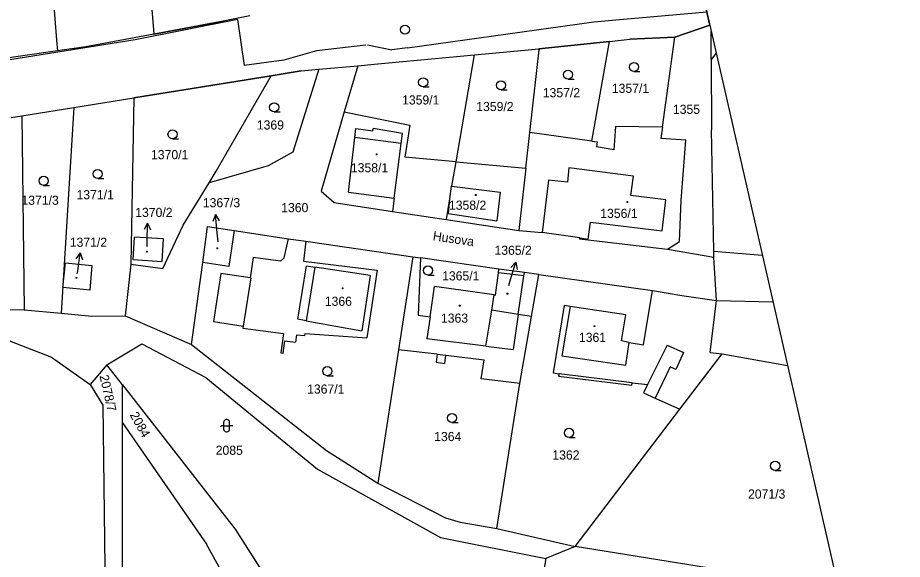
# Model space of a CAD drawing. Extents: x -805730 to -804640, y -1150889 to -1150366.
# Drawn here: x -804785.9 to -804640.4, y -1150604.7 to -1150515.7 of the extents above; entities that cross this region are included whole.
import ezdxf

# ---------------------------------------------------------------- set-up
doc = ezdxf.new("R2010")
doc.units = 0
for name, color, linetype in [('Default', 7, 'Continuous'), ('formát', 7, 'Continuous'), ('kilometráž - vrstava 7', 7, 'Continuous'), ('kn_celek - Cisla parcel pomocna', 7, 'Continuous'), ('kn_celek - Cisla pozemkovych parcel', 7, 'Continuous'), ('kn_celek - Cisla stavebnich parcel', 7, 'Continuous'), ('kn_celek - Dalsi prvky mapy popis', 7, 'Continuous'), ('kn_celek - Hranice parcel', 7, 'Continuous'), ('kn_celek - Vnitrni kresby', 7, 'Continuous'), ('kn_celek - Znacky budov', 7, 'Continuous'), ('kn_celek - Znacky kultur', 7, 'Continuous'), ('plochy - SZDC', 7, 'Continuous'), ('PSR_C2_2_trasa_Vimperk - Kabelová trasa', 7, 'Continuous')]:
    doc.layers.add(name, color=color, linetype=linetype)

# ---------------------------------------------------------------- blocks, each defined once
blk = doc.blocks.new('304')
at = {"layer": 'Default'}
blk.add_line((-0.1, 0), (9.9, 0), dxfattribs=at)
blk.add_circle((-0.1, 7.5), 7.5, dxfattribs=at)
blk = doc.blocks.new('316')
at = {"layer": 'Default'}
for p, q in [((-5, 15.5), (-5, 4.5)), ((0.5, 20), (-0.5, 20)), ((5, 4.5), (5, 15.5)), ((-8.3, 10), (-10, 8.1)), ((-5, 10), (-8.3, 10)), ((-5, 10), (5, 10)), ((-0.5, 0), (0.5, 0)), ((10, 10), (5, 10))]:
    blk.add_line(p, q, dxfattribs=at)
for centre, start, end in [((-0.5, 15.5), 90, 180), ((0.5, 15.5), 0, 90), ((-0.5, 4.5), 180, 270), ((0.5, 4.5), 270, 0)]:
    blk.add_arc(centre, 4.5, start, end, dxfattribs=at)
blk = doc.blocks.new('402')
at = {"layer": 'Default'}
for p, q in [((-0.8, 0.8), (0.7, 0.8)), ((-0.8, 0.8), (-0.8, -0.7)), ((0.7, 0.8), (0.7, -0.7)), ((0.7, -0.7), (-0.8, -0.7))]:
    blk.add_line(p, q, dxfattribs=at)
blk = doc.blocks.new('Z61')
at = {"layer": 'Default'}
for p, q in [((0, 0), (30, 0)), ((30, 0), (19.2, 5.3)), ((30, 0), (19.2, -5.3))]:
    blk.add_line(p, q, dxfattribs=at)

msp = doc.modelspace()

# ---------------------------------------------------------------- linework, layer by layer
at = {"layer": 'formát'}
msp.add_line((-804706.6, -1150365.97), (-804640.43, -1150655.5), dxfattribs=at)
at = {"layer": 'kilometráž - vrstava 7'}
msp.add_circle((-804722.2, -1150517.67), 0.75, dxfattribs=at)
at = {"layer": 'kn_celek - Cisla parcel pomocna'}
for p, q in [((-804752.95, -1150552.55), (-804753.1, -1150551.06)), ((-804764.64, -1150553.33), (-804764.63, -1150552.48)), ((-804776.1, -1150557.81), (-804776.04, -1150557.34)), ((-804705.14, -1150559.73), (-804704.85, -1150558.77))]:
    msp.add_line(p, q, dxfattribs=at)
at = {"layer": 'kn_celek - Hranice parcel'}
for p, q in [((-804765.53, -1150494.1), (-804763.55, -1150517.73)), ((-804781.47, -1150495.86), (-804779.51, -1150519.42)), ((-804747.72, -1150515.43), (-804751.83, -1150516.2)), ((-804763.49, -1150518.4), (-804751.83, -1150516.2)), ((-804763.55, -1150517.73), (-804763.49, -1150518.4)), ((-804672.1, -1150516.95), (-804677.85, -1150518.93)), ((-804671.87, -1150522.56), (-804671.85, -1150518.01)), ((-804779.51, -1150519.42), (-804779.36, -1150521.18)), ((-804763.49, -1150518.4), (-804774.72, -1150520.52)), ((-804688.56, -1150519.6), (-804700.23, -1150520.83)), ((-804691.48, -1150536.01), (-804688.56, -1150519.6)), ((-804688.56, -1150519.6), (-804685.22, -1150519.25)), ((-804677.85, -1150518.93), (-804685.22, -1150519.25)), ((-804679.88, -1150533.68), (-804677.85, -1150518.93)), ((-804779.36, -1150521.18), (-804795.05, -1150523.42)), ((-804774.72, -1150520.52), (-804779.36, -1150521.18)), ((-804710.79, -1150521.81), (-804700.23, -1150520.83)), ((-804701.68, -1150534.6), (-804700.17, -1150521.02)), ((-804700.23, -1150520.83), (-804700.17, -1150521.02)), ((-804727.28, -1150523.34), (-804710.79, -1150521.81)), ((-804713.82, -1150539.42), (-804710.79, -1150521.81)), ((-804671.04, -1150521.56), (-804671.87, -1150522.56)), ((-804671.87, -1150522.56), (-804671.82, -1150534.17)), ((-804736.36, -1150524.18), (-804740.64, -1150537.81)), ((-804739.31, -1150524.46), (-804736.36, -1150524.18)), ((-804736.36, -1150524.18), (-804729.97, -1150523.63)), ((-804729.97, -1150523.63), (-804732.19, -1150531.16)), ((-804729.97, -1150523.63), (-804727.28, -1150523.34)), ((-804744.2, -1150525.25), (-804766.8, -1150528.89)), ((-804753.24, -1150540.95), (-804744.2, -1150525.25)), ((-804739.31, -1150524.46), (-804744.2, -1150525.25)), ((-804776.65, -1150530.47), (-804766.8, -1150528.89)), ((-804766.8, -1150528.89), (-804767.28, -1150556.21)), ((-804785.22, -1150531.85), (-804776.65, -1150530.47)), ((-804776.65, -1150530.47), (-804778.78, -1150564.3)), ((-804732.19, -1150531.16), (-804735.99, -1150544.25)), ((-804732.19, -1150531.16), (-804721.42, -1150533.39)), ((-804786.96, -1150532.13), (-804785.22, -1150531.85)), ((-804785.22, -1150531.85), (-804784.86, -1150563.74)), ((-804721.42, -1150533.39), (-804722.26, -1150538.65)), ((-804687.61, -1150533.6), (-804687.89, -1150537.42)), ((-804679.88, -1150533.68), (-804687.61, -1150533.6)), ((-804679.88, -1150533.68), (-804680.14, -1150535.59)), ((-804671.45, -1150554.09), (-804671.82, -1150534.17)), ((-804702.34, -1150540.46), (-804701.68, -1150534.6)), ((-804691.48, -1150536.01), (-804701.68, -1150534.6)), ((-804676.04, -1150535.83), (-804680.14, -1150535.59)), ((-804676.8, -1150545.77), (-804676.04, -1150535.83)), ((-804691.48, -1150536.01), (-804690.63, -1150536.13)), ((-804690.63, -1150536.13), (-804690.74, -1150536.92)), ((-804687.89, -1150537.42), (-804690.74, -1150536.92)), ((-804740.64, -1150537.81), (-804744.74, -1150540.06)), ((-804713.82, -1150539.42), (-804722.26, -1150538.65)), ((-804744.74, -1150540.06), (-804754.4, -1150542.84)), ((-804714.51, -1150543.42), (-804713.82, -1150539.42)), ((-804713.82, -1150539.42), (-804702.34, -1150540.46)), ((-804754.4, -1150542.84), (-804753.24, -1150540.95)), ((-804702.34, -1150540.46), (-804703.48, -1150550.7)), ((-804758.67, -1150549.81), (-804754.4, -1150542.84)), ((-804735.99, -1150544.25), (-804733.85, -1150546.1)), ((-804714.64, -1150543.4), (-804714.87, -1150545.49)), ((-804714.51, -1150543.42), (-804714.64, -1150543.4)), ((-804714.87, -1150545.49), (-804715.46, -1150548.88)), ((-804677.08, -1150552.48), (-804676.8, -1150545.77)), ((-804733.85, -1150546.1), (-804724.25, -1150547.55)), ((-804724.25, -1150547.55), (-804715.46, -1150548.88)), ((-804715.46, -1150548.88), (-804703.48, -1150550.7)), ((-804762.01, -1150556.95), (-804758.67, -1150549.81)), ((-804755.47, -1150555.94), (-804754.67, -1150550.06)), ((-804754.67, -1150550.06), (-804750.33, -1150550.72)), ((-804766.73, -1150551.77), (-804766.97, -1150555.44)), ((-804761.94, -1150552.09), (-804766.73, -1150551.77)), ((-804750.33, -1150550.72), (-804751.16, -1150556.62)), ((-804750.33, -1150550.72), (-804741.39, -1150552.08)), ((-804703.48, -1150550.7), (-804699.63, -1150551.04)), ((-804693.47, -1150551.91), (-804699.63, -1150551.04)), ((-804762.15, -1150555.77), (-804761.94, -1150552.09)), ((-804742.08, -1150555.2), (-804741.39, -1150552.08)), ((-804741.39, -1150552.08), (-804738.53, -1150552.46)), ((-804738.53, -1150552.46), (-804738.89, -1150555.74)), ((-804738.53, -1150552.46), (-804720.91, -1150555.02)), ((-804693.49, -1150552.09), (-804693.47, -1150551.91)), ((-804693.49, -1150552.09), (-804679.04, -1150553.78)), ((-804679.04, -1150553.78), (-804677.08, -1150552.48)), ((-804679.04, -1150553.78), (-804671.44, -1150555.09)), ((-804671.44, -1150555.09), (-804671.45, -1150554.09)), ((-804671.45, -1150554.09), (-804663.45, -1150554.76)), ((-804778.47, -1150560.05), (-804778.07, -1150555.99)), ((-804778.07, -1150555.99), (-804773.71, -1150556.42)), ((-804766.97, -1150555.44), (-804762.15, -1150555.77)), ((-804757.3, -1150569.44), (-804755.47, -1150555.94)), ((-804751.16, -1150556.62), (-804755.47, -1150555.94)), ((-804747.16, -1150555.14), (-804747.69, -1150558.46)), ((-804742.68, -1150555.76), (-804747.16, -1150555.14)), ((-804742.68, -1150555.76), (-804742.08, -1150555.2)), ((-804738.89, -1150555.74), (-804726.81, -1150557.24)), ((-804720.91, -1150555.02), (-804723.28, -1150570.3)), ((-804720.91, -1150555.02), (-804719.65, -1150555.2)), ((-804719.65, -1150555.2), (-804720.05, -1150564.62)), ((-804706.77, -1150557.03), (-804719.65, -1150555.2)), ((-804670.97, -1150562.21), (-804671.44, -1150555.09)), ((-804773.71, -1150556.42), (-804774.02, -1150560.49)), ((-804767.28, -1150556.21), (-804768.21, -1150564.72)), ((-804767.28, -1150556.21), (-804762.01, -1150556.95)), ((-804726.81, -1150557.24), (-804728.47, -1150568.34)), ((-804707.32, -1150561.31), (-804706.85, -1150557.64)), ((-804706.85, -1150557.64), (-804706.77, -1150557.03)), ((-804702.57, -1150557.62), (-804706.77, -1150557.03)), ((-804700.2, -1150557.94), (-804702.57, -1150557.62)), ((-804752.52, -1150557.74), (-804753.73, -1150565.68)), ((-804747.69, -1150558.46), (-804752.52, -1150557.74)), ((-804701.41, -1150564.85), (-804700.2, -1150557.94)), ((-804700.2, -1150557.94), (-804681.49, -1150560.57)), ((-804774.02, -1150560.49), (-804778.47, -1150560.05)), ((-804718.08, -1150564.9), (-804717.35, -1150559.9)), ((-804707.55, -1150561.25), (-804717.35, -1150559.9)), ((-804707.95, -1150563.81), (-804707.55, -1150561.25)), ((-804707.55, -1150561.25), (-804707.32, -1150561.31)), ((-804682.97, -1150569.49), (-804681.49, -1150560.57)), ((-804681.49, -1150560.57), (-804676.7, -1150561.39)), ((-804676.7, -1150561.39), (-804670.97, -1150562.21)), ((-804696.05, -1150563.02), (-804697.86, -1150574.08)), ((-804695.06, -1150563.17), (-804696.05, -1150563.02)), ((-804685.91, -1150564.57), (-804695.06, -1150563.17)), ((-804672.02, -1150570.73), (-804670.97, -1150562.21)), ((-804670.97, -1150562.21), (-804661.7, -1150562.42)), ((-804792.7, -1150563.59), (-804784.86, -1150563.74)), ((-804784.86, -1150563.74), (-804778.78, -1150564.3)), ((-804778.78, -1150564.3), (-804773.73, -1150564.76)), ((-804773.73, -1150564.76), (-804768.21, -1150564.72)), ((-804768.21, -1150564.72), (-804757.3, -1150569.44)), ((-804720.05, -1150564.62), (-804718.08, -1150564.9)), ((-804703.6, -1150564.5), (-804707.95, -1150563.81)), ((-804701.41, -1150564.85), (-804703.6, -1150564.5)), ((-804703.33, -1150575.86), (-804701.41, -1150564.85)), ((-804686.63, -1150568.85), (-804685.91, -1150564.57)), ((-804753.73, -1150565.68), (-804748.85, -1150566.42)), ((-804791.75, -1150567.1), (-804780.37, -1150571.54)), ((-804748.85, -1150566.42), (-804748.89, -1150566.77)), ((-804748.89, -1150566.77), (-804742.21, -1150567.6)), ((-804742.21, -1150567.6), (-804742.62, -1150570.83)), ((-804738.67, -1150567.97), (-804738.65, -1150567.62)), ((-804738.65, -1150567.62), (-804728.47, -1150568.34)), ((-804742.25, -1150570.88), (-804742, -1150568.85)), ((-804742, -1150568.85), (-804740.23, -1150569.07)), ((-804740.08, -1150567.87), (-804740.23, -1150569.07)), ((-804740.08, -1150567.87), (-804738.67, -1150567.97)), ((-804685.35, -1150569.09), (-804686.63, -1150568.85)), ((-804685.35, -1150569.09), (-804682.97, -1150569.49)), ((-804771.23, -1150572.75), (-804765.48, -1150569.34)), ((-804765.48, -1150569.34), (-804754.97, -1150574.87)), ((-804757.3, -1150569.44), (-804735.14, -1150586.85)), ((-804723.28, -1150570.3), (-804726.69, -1150592.24)), ((-804716.93, -1150571.04), (-804723.28, -1150570.3)), ((-804672.02, -1150570.73), (-804670.08, -1150570.98)), ((-804780.37, -1150571.54), (-804773.99, -1150576)), ((-804742.62, -1150570.83), (-804742.25, -1150570.88)), ((-804716.93, -1150571.04), (-804717.08, -1150572.33)), ((-804715.65, -1150572.54), (-804715.49, -1150571.21)), ((-804715.49, -1150571.21), (-804709.22, -1150571.94)), ((-804709.68, -1150575.1), (-804709.22, -1150571.94)), ((-804677.01, -1150580.07), (-804670.08, -1150570.98)), ((-804670.08, -1150570.98), (-804659.31, -1150572.9)), ((-804771.23, -1150572.75), (-804773.99, -1150576)), ((-804768.67, -1150576.05), (-804771.23, -1150572.75)), ((-804717.08, -1150572.33), (-804715.65, -1150572.54)), ((-804754.97, -1150574.87), (-804736.59, -1150589.91)), ((-804703.33, -1150575.86), (-804709.68, -1150575.1)), ((-804697.86, -1150574.08), (-804696.86, -1150574.23)), ((-804696.86, -1150574.23), (-804696.95, -1150574.63)), ((-804696.95, -1150574.63), (-804684.89, -1150576.12)), ((-804773.99, -1150576), (-804771.91, -1150579.38)), ((-804768.67, -1150582.3), (-804768.67, -1150576.05)), ((-804768.67, -1150576.05), (-804750.12, -1150599.8)), ((-804707.1, -1150599.7), (-804703.33, -1150575.86)), ((-804684.89, -1150576.12), (-804684.84, -1150575.72)), ((-804684.84, -1150575.72), (-804682.31, -1150576.03)), ((-804682.31, -1150576.03), (-804682.98, -1150577.37)), ((-804682.98, -1150577.37), (-804681.05, -1150578.24)), ((-804771.91, -1150579.38), (-804771.55, -1150606.03)), ((-804681.05, -1150578.24), (-804677.01, -1150580.07)), ((-804694.22, -1150602.66), (-804677.01, -1150580.07)), ((-804768.69, -1150606.23), (-804768.67, -1150582.3)), ((-804768.67, -1150582.3), (-804754.83, -1150602.27)), ((-804735.14, -1150586.85), (-804726.69, -1150592.24)), ((-804736.59, -1150589.91), (-804716.38, -1150601.17)), ((-804726.69, -1150592.24), (-804715.56, -1150597.91)), ((-804715.56, -1150597.91), (-804713.12, -1150598.64)), ((-804750.12, -1150599.8), (-804728.74, -1150633.39)), ((-804713.12, -1150598.64), (-804707.1, -1150599.7)), ((-804707.1, -1150599.7), (-804694.22, -1150602.66)), ((-804716.38, -1150601.17), (-804699.05, -1150604.64)), ((-804739.17, -1150630.73), (-804754.83, -1150602.27)), ((-804694.22, -1150602.66), (-804699.05, -1150604.64)), ((-804653.81, -1150609.12), (-804694.22, -1150602.66)), ((-804699.05, -1150604.64), (-804701.95, -1150620.52))]:
    msp.add_line(p, q, dxfattribs=at)
at = {"layer": 'kn_celek - Vnitrni kresby'}
for p, q in [((-804730.44, -1150535.43), (-804730.29, -1150533.9)), ((-804730.29, -1150533.9), (-804727.51, -1150534.31)), ((-804727.51, -1150534.31), (-804727.44, -1150533.95)), ((-804722.63, -1150534.73), (-804727.44, -1150533.95)), ((-804731.53, -1150544.37), (-804730.44, -1150535.43)), ((-804722.82, -1150536.38), (-804730.44, -1150535.43)), ((-804722.82, -1150536.38), (-804722.63, -1150534.73)), ((-804723.97, -1150545.37), (-804722.82, -1150536.38)), ((-804695.25, -1150540.37), (-804695.49, -1150542.73)), ((-804684.65, -1150541.76), (-804695.25, -1150540.37)), ((-804698.62, -1150542.42), (-804699.63, -1150551.04)), ((-804695.49, -1150542.73), (-804698.62, -1150542.42)), ((-804685.06, -1150544.92), (-804684.65, -1150541.76)), ((-804731.53, -1150544.37), (-804723.97, -1150545.37)), ((-804714.51, -1150543.42), (-804706.54, -1150544.38)), ((-804706.54, -1150544.38), (-804707.12, -1150549.13)), ((-804723.97, -1150545.37), (-804724.25, -1150547.55)), ((-804714.87, -1150545.49), (-804715.14, -1150547.92)), ((-804679.32, -1150545.66), (-804685.06, -1150544.92)), ((-804679.93, -1150550.77), (-804679.32, -1150545.66)), ((-804715.14, -1150547.92), (-804707.12, -1150549.13)), ((-804692.11, -1150552.1), (-804691.71, -1150549.33)), ((-804691.71, -1150549.33), (-804679.93, -1150550.77)), ((-804693.47, -1150551.91), (-804692.11, -1150552.1)), ((-804739.85, -1150565.28), (-804738.41, -1150556.49)), ((-804737.03, -1150556.7), (-804738.47, -1150565.53)), ((-804738.41, -1150556.49), (-804737.03, -1150556.7)), ((-804727.95, -1150558.1), (-804737.03, -1150556.7)), ((-804702.65, -1150558.17), (-804706.85, -1150557.64)), ((-804702.65, -1150558.17), (-804702.57, -1150557.62)), ((-804747.55, -1150558.47), (-804748.85, -1150566.42)), ((-804747.55, -1150558.47), (-804747.69, -1150558.46)), ((-804727.95, -1150558.1), (-804729.3, -1150567.19)), ((-804703.6, -1150564.5), (-804702.65, -1150558.17)), ((-804695.06, -1150563.17), (-804696.44, -1150571.27)), ((-804718.08, -1150564.9), (-804718.6, -1150568.49)), ((-804708.9, -1150569.7), (-804707.95, -1150563.81)), ((-804703.6, -1150564.5), (-804704.45, -1150570.25)), ((-804738.47, -1150565.53), (-804739.85, -1150565.28)), ((-804738.47, -1150565.53), (-804729.3, -1150567.19)), ((-804708.9, -1150569.7), (-804718.6, -1150568.49)), ((-804685.91, -1150572.82), (-804685.35, -1150569.09)), ((-804708.9, -1150569.7), (-804704.45, -1150570.25)), ((-804679.08, -1150569.57), (-804682.31, -1150576.03)), ((-804679.08, -1150569.57), (-804676.4, -1150570.73)), ((-804676.4, -1150570.73), (-804677.65, -1150573.57)), ((-804716.93, -1150571.04), (-804715.49, -1150571.21)), ((-804696.44, -1150571.27), (-804685.91, -1150572.82)), ((-804678.6, -1150573.12), (-804681.05, -1150578.24)), ((-804677.65, -1150573.57), (-804678.6, -1150573.12)), ((-804684.84, -1150575.72), (-804696.86, -1150574.23))]:
    msp.add_line(p, q, dxfattribs=at)
at = {"layer": 'plochy - SZDC'}
for p, q in [((-804672.1, -1150516.95), (-804674.73, -1150505.41)), ((-804747.72, -1150515.43), (-804751.83, -1150516.2)), ((-804751.83, -1150516.2), (-804763.49, -1150518.4)), ((-804677.85, -1150518.93), (-804672.1, -1150516.95)), ((-804763.49, -1150518.4), (-804774.72, -1150520.52)), ((-804700.23, -1150520.83), (-804688.56, -1150519.6)), ((-804688.56, -1150519.6), (-804685.22, -1150519.25)), ((-804685.22, -1150519.25), (-804677.85, -1150518.93)), ((-804779.36, -1150521.18), (-804795.05, -1150523.42)), ((-804774.72, -1150520.52), (-804779.36, -1150521.18)), ((-804710.79, -1150521.81), (-804700.23, -1150520.83)), ((-804727.28, -1150523.34), (-804710.79, -1150521.81)), ((-804739.31, -1150524.46), (-804736.36, -1150524.18)), ((-804736.36, -1150524.18), (-804729.97, -1150523.63)), ((-804729.97, -1150523.63), (-804727.28, -1150523.34)), ((-804766.8, -1150528.89), (-804744.2, -1150525.25)), ((-804744.2, -1150525.25), (-804739.31, -1150524.46)), ((-804776.65, -1150530.47), (-804766.8, -1150528.89)), ((-804785.22, -1150531.85), (-804776.65, -1150530.47)), ((-804786.96, -1150532.13), (-804785.22, -1150531.85))]:
    msp.add_line(p, q, dxfattribs=at)
at = {"layer": 'PSR_C2_2_trasa_Vimperk - Kabelová trasa'}
for p, q in [((-804688.16, -1150516.11), (-804672.6, -1150514.73)), ((-804749.78, -1150515.99), (-804766.6, -1150519.35)), ((-804749.78, -1150515.99), (-804748.68, -1150523.55)), ((-804721.8, -1150520.64), (-804691.14, -1150516.38)), ((-804691.14, -1150516.38), (-804688.16, -1150516.11)), ((-804736.74, -1150521.15), (-804742.12, -1150522.72)), ((-804728.64, -1150520.2), (-804736.74, -1150521.15)), ((-804728.36, -1150520.17), (-804724.38, -1150520.97)), ((-804721.8, -1150520.64), (-804724.38, -1150520.97)), ((-804742.12, -1150522.72), (-804748.68, -1150523.55))]:
    msp.add_line(p, q, dxfattribs=at)
msp.add_lwpolyline([(-804766.6, -1150519.35), (-804794.79, -1150523.86), (-804834.76, -1150530), (-804846.51, -1150532.09)], dxfattribs=at)

# ---------------------------------------------------------------- block references
at = {"layer": 'kn_celek - Cisla parcel pomocna'}
for p, xscale, yscale, rotation in [((-804753.1, -1150551.06), 0.09999999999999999, 0.10000000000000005, 95.59737000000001), ((-804764.63, -1150552.48), 0.1, 0.09999999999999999, 89.10720000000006), ((-804776.04, -1150557.34), 0.1, 0.09999999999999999, 82.54719000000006), ((-804704.85, -1150558.77), 0.09999999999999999, 0.10000000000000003, 73.03959000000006)]:
    msp.add_blockref('Z61', p, dxfattribs=dict(at, xscale=xscale, yscale=yscale, rotation=rotation))
at = {"layer": 'kn_celek - Znacky budov', "xscale": 0.1, "yscale": 0.10000000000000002}
for p in [(-804726.9, -1150538.16), (-804710.58, -1150544.86), (-804685.67, -1150546.03), (-804764.67, -1150554.16), (-804753.09, -1150553.63), (-804776.27, -1150558.48), (-804732.49, -1150560.21), (-804705.37, -1150561.09), (-804713.22, -1150563.06), (-804691.09, -1150566.43)]:
    msp.add_blockref('402', p, dxfattribs=at)
at = {"layer": 'kn_celek - Znacky kultur', "xscale": 0.1, "yscale": 0.10000000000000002}
for name, p in [('304', (-804684.56, -1150524.58)), ('304', (-804719.21, -1150527.08)), ('304', (-804695.38, -1150525.82)), ('304', (-804706.4, -1150527.57)), ('304', (-804743.72, -1150531.19)), ('304', (-804760.43, -1150535.63)), ('304', (-804772.74, -1150542.15)), ('304', (-804781.64, -1150543.27)), ('304', (-804718.41, -1150558.01)), ('304', (-804734.98, -1150574.56)), ('304', (-804714.48, -1150582.26)), ('316', (-804751.55, -1150583.78)), ('304', (-804695.23, -1150584.71)), ('304', (-804661.33, -1150590.13))]:
    msp.add_blockref(name, p, dxfattribs=at)

# ---------------------------------------------------------------- texts
at = {"layer": 'kn_celek - Cisla parcel pomocna'}
for s, p in [('1367/3', (-804755.46, -1150546.87)), ('1370/2', (-804766.57, -1150548.47)), ('1371/2', (-804777.34, -1150553.37)), ('1365/2', (-804707.5, -1150554.69))]:
    msp.add_text(s, height=1.5, dxfattribs=at).set_placement(p)
at = {"layer": 'kn_celek - Cisla pozemkovych parcel'}
for s, p in [('1357/1', (-804688.2, -1150528.07)), ('1359/1', (-804722.69, -1150529.98)), ('1357/2', (-804699.55, -1150528.79)), ('1359/2', (-804710.49, -1150531.06)), ('1355', (-804678.15, -1150531.52)), ('1369', (-804746.58, -1150534.09)), ('1370/1', (-804763.98, -1150538.97)), ('1371/1', (-804776.23, -1150545.56)), ('1371/3', (-804785.29, -1150546.47)), ('1360', (-804742.57, -1150547.68)), ('1365/1', (-804716.11, -1150558.9)), ('1367/1', (-804738.31, -1150577.51)), ('1364', (-804717.41, -1150585.31)), ('2085', (-804753.34, -1150587.57)), ('1362', (-804697.98, -1150588.35)), ('2071/3', (-804665.8, -1150594.76))]:
    msp.add_text(s, height=1.5, dxfattribs=at).set_placement(p)
for s, rotation, p in [('2078/7', 282.8076, (-804772.46, -1150574.6)), ('2084', 299.0926, (-804767.52, -1150581))]:
    msp.add_text(s, height=1.5, rotation=rotation, dxfattribs=at).set_placement(p)
at = {"layer": 'kn_celek - Cisla stavebnich parcel'}
for s, height, p in [('1358/1', 1.5, (-804731.11, -1150541.13)), ('1358/2', 1.5, (-804714.98, -1150547.28)), ('1356/1', 1.5, (-804690.1, -1150548.63)), ('1370/2', 0.1, (-804764.91, -1150553.3)), ('1367/3', 0.1, (-804753.22, -1150552.52)), ('1371/2', 0.1, (-804776.36, -1150557.78)), ('1365/2', 0.1, (-804705.41, -1150559.7)), ('1366', 1.5, (-804735.4, -1150563.08)), ('1363', 1.5, (-804716.3, -1150565.85)), ('1361', 1.5, (-804693.61, -1150569.01))]:
    msp.add_text(s, height=height, dxfattribs=at).set_placement(p)
at = {"layer": 'kn_celek - Dalsi prvky mapy popis'}
msp.add_text('Husova', height=1.5, rotation=351.5394, dxfattribs=at).set_placement((-804717.7, -1150552.29))

doc.saveas('drawing.dxf')
